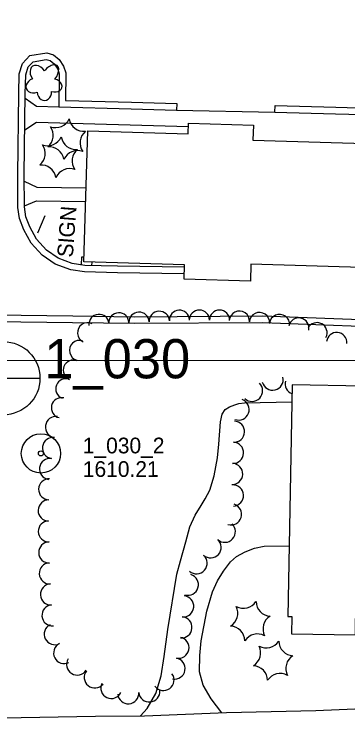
# Model space of a CAD drawing. Extents: x 189384 to 193282, y 256970 to 260388.
# Drawn here: x 190753.6 to 190881.2, y 259874.1 to 260143.9 of the extents above; entities that cross this region are included whole.
import ezdxf

# ---------------------------------------------------------------- set-up
doc = ezdxf.new("R2010")
doc.units = 0
for name, color, linetype in [('E_DWY', 7, 'Continuous'), ('E_LAND_Vegetation', 7, 'Continuous'), ('E_MAP_GridLines', 7, 'Continuous'), ('E_MAP_Limits', 7, 'Continuous'), ('E_MAP_PassPoints', 7, 'Continuous'), ('E_MISCPROP', 7, 'Continuous'), ('E_MISCPROP_HvyLine', 7, 'Continuous'), ('E_PATH_Sidewalk', 7, 'Continuous'), ('E_RDWY', 7, 'Continuous')]:
    doc.layers.add(name, color=color, linetype=linetype)

# ---------------------------------------------------------------- blocks, each defined once
blk = doc.blocks.new('PP')
at = {"layer": 'E_MAP_PassPoints'}
for radius in [7.5, 0.96]:
    blk.add_circle((0, 0), radius, dxfattribs=at)
blk = doc.blocks.new('PHOTOC')
at = {"layer": 'E_MAP_Limits'}
for p, q in [((0.12, 14.06), (0.06, -13.8)), ((-13.79, 0.03), (14.12, 0.01))]:
    blk.add_line(p, q, dxfattribs=at)
blk.add_circle((0.17, 0.03), 14, dxfattribs=at)
blk = doc.blocks.new('PINEL')
at = {"layer": 'E_LAND_Vegetation'}
for centre, start, end in [((-8.23, 7.26), 275.2112, 0.9761), ((2.17, 10.66), 215.2112, 300.9761), ((10.31, 3.35), 155.2112, 240.9761), ((-10.49, -3.45), 335.2112, 60.9761), ((8.05, -7.36), 95.2112, 180.9761), ((-2.35, -10.75), 35.2112, 120.9761)]:
    blk.add_arc(centre, 5.72, start, end, dxfattribs=at)
blk = doc.blocks.new('SIGN')
at = {"layer": 'E_MISCPROP'}
blk.add_text('SIGN', height=6, rotation=0, dxfattribs=at).set_placement((0, -3))
blk = doc.blocks.new('TREE')
at = {"layer": 'E_LAND_Vegetation'}
for centre, major_axis, ratio in [((-1.07, 3.38), (0.91, -3.32), 0.782863), ((-3.74, -0.07), (3.29, -0.08), 0.832022), ((2.88, 1.66), (-3.52, -1.95), 0.691916), ((2.54, -2.64), (-3.34, 3.06), 0.560249), ((-1.48, -3.66), (1.2, 3.24), 0.716896)]:
    blk.add_ellipse(centre, major_axis=major_axis, ratio=ratio, start_param=1.570796, end_param=4.712389, dxfattribs=at)

msp = doc.modelspace()

# ---------------------------------------------------------------- linework, layer by layer
at = {"layer": 'E_DWY'}
for points in [[(190853.32, 260106.4), (190853.38, 260108.9), (190876.53, 260108.3), (190906.8, 260107.47), (190932.13, 260106.9), (190954.36, 260106.31), (190954.45, 260115.82), (190955, 260121.63), (190956.58, 260126.8), (190959.01, 260131.98), (190962.51, 260136), (190966.5, 260139.36), (190970.5, 260141.43), (190975.26, 260143.16), (190978.93, 260143.86), (190982.62, 260143.88), (190991.88, 260143.46), (190998.35, 260143.14), (191002.44, 260142.41), (191006.15, 260140.77), (191008.25, 260138.62), (191009.83, 260136.23), (191011.08, 260133.34)], [(190853.32, 260106.4), (190876.47, 260105.8), (190906.74, 260104.97), (190932.06, 260104.4), (190956.83, 260103.74), (190956.94, 260115.69), (190957.46, 260121.14), (190958.92, 260125.9), (190961.13, 260130.6), (190964.27, 260134.21), (190967.89, 260137.26), (190971.5, 260139.14), (190975.92, 260140.74), (190979.18, 260141.36), (190982.57, 260141.38), (190991.76, 260140.96), (190998.07, 260140.65), (191001.7, 260140), (191004.7, 260138.68), (191006.3, 260137.04), (191007.63, 260135.04), (191008.79, 260132.35)], [(190818.65, 260044.64), (190793.11, 260044.99), (190780.44, 260045.32), (190775.21, 260046.14), (190769.31, 260048.34), (190764.34, 260051.69), (190760.13, 260056.38), (190757.34, 260061.44), (190755.61, 260065.78), (190755.06, 260069.98), (190754.97, 260082.4), (190755.33, 260113.49), (190755.52, 260121.07), (190756.76, 260125.01), (190759.59, 260128), (190766.05, 260129.12), (190768.62, 260128.34), (190770.8, 260126.54), (190772.52, 260123.99), (190773.37, 260121.41), (190773.26, 260110.85), (190798.4, 260110.18), (190815.79, 260109.72), (190815.72, 260107.22)], [(190818.72, 260047.14), (190793.16, 260047.49), (190780.67, 260047.81), (190775.84, 260048.57), (190770.47, 260050.58), (190765.99, 260053.59), (190762.19, 260057.84), (190759.6, 260062.51), (190758.05, 260066.41), (190757.56, 260070.16), (190757.47, 260082.39), (190757.83, 260113.45), (190758.01, 260120.65), (190758.97, 260123.71), (190760.83, 260125.68), (190765.89, 260126.56), (190767.42, 260126.09), (190768.93, 260124.84), (190770.25, 260122.88), (190770.87, 260121.02), (190770.73, 260108.42), (190798.34, 260107.68), (190815.72, 260107.22)], [(190815.72, 260107.22), (190853.32, 260106.4)], [(190711.1, 260029.14), (190746.2, 260028.86), (190776, 260028.51), (190799.66, 260028.22), (190848.68, 260028.54), (190882.51, 260027.22), (190914.01, 260026.95), (190936.63, 260026.6), (190955.37, 260026.14), (190967.76, 260025.44), (190981.75, 260024.16), (190988.44, 260023.29), (190992.75, 260022.33), (190997.03, 260019.84), (190999.26, 260016.65), (191000.65, 260012.6), (191001.4, 260008.55)], [(190711.08, 260026.64), (190746.18, 260026.36), (190775.97, 260026.01), (190799.66, 260025.72), (190848.64, 260026.04), (190882.45, 260024.72), (190913.98, 260024.45), (190936.58, 260024.1), (190955.27, 260023.64), (190967.58, 260022.95), (190981.47, 260021.68), (190988, 260020.82), (190991.83, 260019.97), (190995.29, 260017.95), (190997.01, 260015.5), (190998.22, 260011.96), (190998.94, 260008.09)], [(190832.51, 259988.04), (190833.18, 259990.93), (190834.31, 259992.78), (190835.96, 259993.81), (190837.91, 259994.58), (190839.47, 259995.02), (190841.62, 259995.3), (190859.75, 259995.69)], [(190801.85, 259875.58), (190804.46, 259878.4), (190807.73, 259884.15), (190809.75, 259890.95), (190810.95, 259898.36), (190812.3, 259908.57), (190815.8, 259929.73), (190817.19, 259934.94), (190819.18, 259942.12), (190820.81, 259947.84), (190822.74, 259952.32), (190825.12, 259955.99), (190826.63, 259958.61), (190828.47, 259961.84), (190830.12, 259967.37), (190831.37, 259974.2), (190831.79, 259979.43), (190832.51, 259988.04)], [(190833.05, 259876.8), (190828.86, 259882.09), (190825.81, 259887.41), (190824.42, 259892.48), (190824.58, 259898.65), (190825.06, 259904.26), (190827.27, 259915.7), (190829.43, 259923.09), (190831.39, 259927.2), (190833.67, 259930.95), (190836.35, 259934.54), (190838.58, 259936.55), (190841.89, 259938.37), (190845.43, 259939.72), (190849.21, 259940.52), (190858.74, 259940.63)]]:
    msp.add_lwpolyline(points, dxfattribs=at)
at = {"layer": 'E_LAND_Vegetation'}
for centre, radius, start, end in [((190793.62, 260025.85), 3.86, 1.8938, 181.8938), ((190801.33, 260026.1), 3.86, 1.8938, 181.8938), ((190809.08, 260026.43), 3.86, 2.9291, 182.9291), ((190816.79, 260026.83), 3.86, 2.9291, 182.9291), ((190824.41, 260026.89), 3.86, 359.9923, 179.9923), ((190832.13, 260026.88), 3.86, 359.9923, 179.9923), ((190839.71, 260026.51), 3.86, 355.9437, 175.9437), ((190847.41, 260025.96), 3.86, 355.9437, 175.9437), ((190786.04, 260025.26), 3.86, 5.4965, 185.4965), ((190855.05, 260025.23), 3.86, 354.3771, 174.3771), ((190862.43, 260023.89), 3.86, 347.9446, 167.9446), ((190781.69, 260022.05), 3.86, 64.2413, 244.2413), ((190869.39, 260022.09), 3.86, 332.3258, 152.3258), ((190876.92, 260018.34), 3.86, 354.9603, 174.9603), ((190778.62, 260015.3), 3.86, 73.495, 253.495), ((190776.24, 260007.79), 3.86, 68.1548, 248.1548), ((190773.36, 260000.62), 3.86, 68.1548, 248.1548), ((190844.55, 259999.87), 4.04, 226.1813, 46.1659), ((190852.41, 260004.14), 4.04, 193.1588, 13.1435), ((190861.2, 260002.61), 4.04, 165.5475, 249.8168), ((190771.7, 259993.38), 3.86, 77.1414, 257.1414), ((190839.42, 259992.74), 4.04, 249.5588, 69.5434), ((190769.6, 259986.01), 4.04, 81.8648, 261.8495), ((190837.65, 259984.25), 4.04, 267.2959, 87.2806), ((190768.46, 259978.01), 4.04, 81.8648, 261.8495), ((190837.28, 259976.17), 4.04, 267.6094, 87.594), ((190767.31, 259970.02), 4.04, 81.8648, 261.8495), ((190836.94, 259968.11), 4.04, 267.6094, 87.594), ((190767.01, 259962.21), 4.04, 88.6881, 268.6728), ((190837.26, 259959.85), 4.04, 272.8357, 92.8204), ((190766.82, 259954.14), 4.04, 88.6881, 268.6728), ((190836.53, 259952.67), 4.04, 252.6143, 72.599), ((190766.86, 259946.15), 4.04, 91.1551, 271.1398), ((190834.16, 259946), 4.04, 227.4979, 47.4826), ((190767.02, 259938.08), 4.04, 91.1551, 271.1398), ((190828.71, 259940.05), 4.04, 227.4979, 47.4826), ((190823.34, 259933.96), 4.04, 228.6375, 48.6222), ((190767.25, 259930.08), 4.04, 93.0958, 273.0805), ((190820.01, 259925.75), 4.04, 253.4067, 73.3914), ((190767.69, 259922.02), 4.04, 93.0958, 273.0805), ((190818.22, 259917.47), 4.04, 265.279, 85.2636), ((190768.26, 259914.03), 4.04, 94.8341, 274.8188), ((190817.56, 259909.42), 4.04, 265.279, 85.2636), ((190769.13, 259906.86), 4.04, 116.3899, 296.3746), ((190816.41, 259901.66), 4.04, 259.4462, 79.4309), ((190772.72, 259899.62), 4.04, 116.3899, 296.3746), ((190777.7, 259895.25), 4.04, 148.5252, 328.5099), ((190814.93, 259893.72), 4.04, 259.4462, 79.4309), ((190784.43, 259890.33), 4.04, 141.0058, 320.9904), ((190810.68, 259889.34), 4.04, 216.4784, 36.463), ((190790.74, 259886.3), 4.04, 155.2936, 335.2783), ((190797.22, 259884.27), 4.04, 184.8331, 4.8177), ((190805.27, 259884.95), 4.04, 184.8331, 4.8177)]:
    msp.add_arc(centre, radius, start, end, dxfattribs=at)
at = {"layer": 'E_MAP_GridLines'}
msp.add_line((190145.98, 260011.08), (191645.98, 260012.15), dxfattribs=at)
msp.add_line((190145.98, 260011.08), (191645.98, 260012.15), dxfattribs=at)
at = {"layer": 'E_MISCPROP'}
msp.add_line((190762.68, 260060.25), (190765.52, 260066.91), dxfattribs=at)
at = {"layer": 'E_MISCPROP_HvyLine'}
for points in [[(190780.23, 260049.13), (190781.72, 260099.24), (190781.72, 260099.24), (190820.11, 260098.1), (190820.11, 260098.1), (190820.23, 260102.13), (190820.23, 260102.13), (190845.08, 260101.39), (190845.08, 260101.39), (190845.08, 260101.39), (190844.91, 260095.7), (190844.91, 260095.7), (190892.03, 260094.3), (190890.62, 260046.91), (190890.62, 260046.91), (190890.62, 260046.91), (190844.09, 260048.29), (190843.9, 260041.85), (190843.9, 260041.85), (190818.59, 260042.61), (190818.75, 260047.99), (190818.75, 260047.99), (190780.23, 260049.13)], [(190859.87, 260002.18), (190858.24, 259913.6), (190858.24, 259913.6), (190858.24, 259913.6), (190859.7, 259913.58), (190859.7, 259913.58), (190859.58, 259907.04), (190884.05, 259906.59), (190884.05, 259906.59), (190884.16, 259912.83), (190884.16, 259912.83), (190884.16, 259912.83), (190885.63, 259912.81), (190885.63, 259912.81), (190887.27, 260001.67), (190859.87, 260002.18)]]:
    msp.add_lwpolyline(points, close=True, dxfattribs=at)
at = {"layer": 'E_PATH_Sidewalk'}
for points in [[(190757.81, 260111.74), (190762.14, 260108.65), (190770.73, 260108.42)], [(190757.67, 260099.64), (190762.14, 260102.55), (190820.2, 260100.92)], [(190757.48, 260080.02), (190762.21, 260077.79), (190781.08, 260077.44)], [(190757.55, 260070.63), (190762.2, 260072.56), (190780.92, 260072.22)], [(190779.29, 260048.03), (190779.44, 260051.13), (190780.29, 260051.11)], [(190783.36, 260047.74), (190783.44, 260049.04)]]:
    msp.add_lwpolyline(points, dxfattribs=at)
at = {"layer": 'E_RDWY'}
msp.add_lwpolyline([(190614.18, 259874.08), (190643.27, 259874.25), (190673.64, 259874.33), (190713.05, 259874.38), (190749.1, 259874.89), (190784.75, 259875.49), (190803.44, 259875.58), (190834.79, 259876.88), (190868.89, 259877.7), (190910.69, 259879.44), (190934.84, 259880.17), (190958.89, 259883.07), (190971.15, 259885.9), (190978.41, 259888.91), (190984.49, 259892.96)], dxfattribs=at)

# ---------------------------------------------------------------- block references
at = {"layer": 'E_LAND_Vegetation', "xscale": 1.0000021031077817, "yscale": 1.0000021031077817}
for name, p, rotation in [('TREE', (190764.77, 260117.88), 94.4633825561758), ('PINEL', (190773.59, 260096.19), 94.4633823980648), ('PINEL', (190770.54, 260089.27), 94.46338245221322)]:
    msp.add_blockref(name, p, dxfattribs=dict(at, rotation=rotation))
at = {"layer": 'E_LAND_Vegetation'}
for p, rotation in [((190843.89, 259911.92), 86.032976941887), ((190852.6, 259896.79), 86.03297678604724)]:
    msp.add_blockref('PINEL', p, dxfattribs=dict(at, rotation=rotation))
at = {"layer": 'E_MAP_Limits', "rotation": 0.04071536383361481}
msp.add_blockref('PHOTOC', (190749.31, 260004.65), dxfattribs=at)
msp.add_blockref('PHOTOC', (190749.31, 260004.65), dxfattribs=at)
at = {"layer": 'E_MAP_PassPoints', "rotation": 0.04071510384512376}
msp.add_blockref('PP', (190763.84, 259975.95), dxfattribs=at)
msp.add_blockref('PP', (190763.84, 259975.95), dxfattribs=at)
at = {"layer": 'E_MISCPROP', "rotation": 85.5987712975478}
msp.add_blockref('SIGN', (190773.01, 260050.94), dxfattribs=at)

# ---------------------------------------------------------------- texts
at = {"layer": 'E_MAP_Limits'}
msp.add_text('1_030', height=15, rotation=0.0407, dxfattribs=at).set_placement((190765.14, 260004.62))
msp.add_text('1_030', height=15, rotation=0.0407, dxfattribs=at).set_placement((190765.14, 260004.62))
at = {"layer": 'E_MAP_PassPoints'}
for s, p in [('1_030_2', (190779.84, 259975.96)), ('1_030_2', (190779.84, 259975.96)), ('1610.21', (190779.85, 259966.96)), ('1610.21', (190779.85, 259966.96))]:
    msp.add_text(s, height=6, rotation=0.0407, dxfattribs=at).set_placement(p)

doc.saveas('drawing.dxf')
